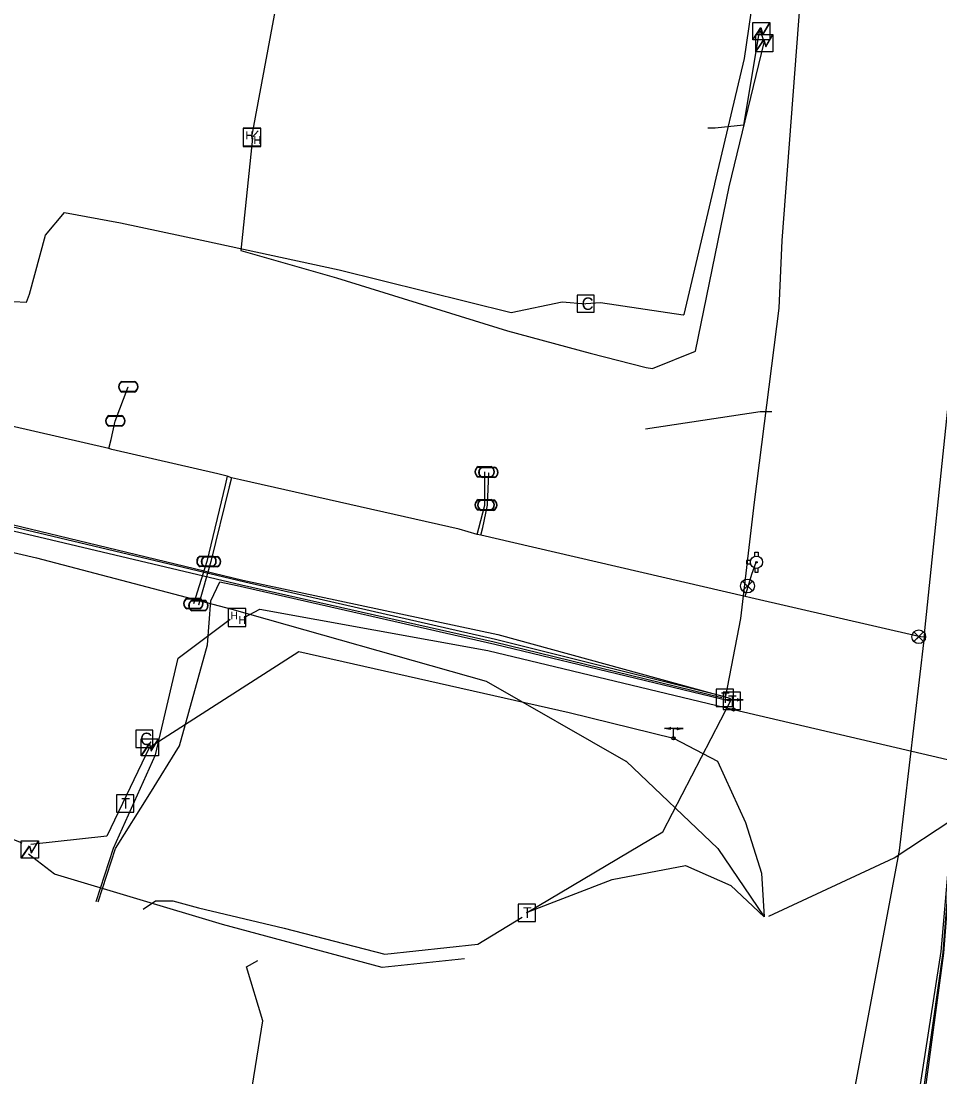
# Model space of a CAD drawing. Extents: x 2070721 to 2083039, y 729290 to 737883.
# Drawn here: x 2082067.8 to 2082364.3, y 736148.2 to 736489 of the extents above; entities that cross this region are included whole.
import ezdxf

# ---------------------------------------------------------------- set-up
doc = ezdxf.new("R2010")
doc.units = 0
for name, color, linetype in [('Cogo Default Point CELL', 7, 'Continuous'), ('COGO Default Point Elevation', 7, 'Continuous'), ('COGO Default Point Number', 7, 'Continuous'), ('Exist Utilities Power Pole CELL', 7, 'Continuous'), ('Exist Utilities Power Pole Cogo Elevation', 7, 'Continuous'), ('Exist Utilities Power UG Cable Cogo Point CELL', 7, 'Continuous'), ('Exist Utilities Telephone UG Cable SUE LOS C Cogo Elevation', 7, 'Continuous'), ('Exist Utilities Telephone UG Cable SUE LOS C Cogo Number', 7, 'Continuous'), ('Exist Utilities Telephone UG FO Cogo Point CELL', 7, 'Continuous'), ('Exist Utilities Telephone UG FO SUE LOS B Cogo Comment', 7, 'Continuous'), ('Exist Utilities Telephone UG FO SUE LOS B Cogo Number', 7, 'Continuous'), ('Exist Utilities TV Pedestal Cogo Elevation', 7, 'Continuous'), ('Exist Utilities TV UG Cable Cogo Point CELL', 7, 'Continuous'), ('Exist Utilities TV UG Cable SUE LOS C Cogo Comment', 7, 'Continuous'), ('Exist Utilities TV UG Cable SUE LOS C Cogo Elevation', 7, 'Continuous'), ('Exist Utilities TV UG Cable SUE LOS C Cogo Point CELL', 7, 'Continuous'), ('Exist Utilities Water UG Line SUE Cogo Point CELL', 7, 'Continuous'), ('Exist Utilities Water UG Line SUE LOS B Cogo Number', 7, 'Continuous')]:
    doc.layers.add(name, color=color, linetype=linetype)

msp = doc.modelspace()

# ---------------------------------------------------------------- linework, layer by layer
at = {"layer": 'Cogo Default Point CELL'}
for p, q in [((2082249.96, 736397.77), (2082249.96, 736397.77)), ((2082107.52, 736257.33), (2082107.52, 736257.33))]:
    msp.add_line(p, q, dxfattribs=at)
for points in [[(2082247.18, 736394.99), (2082252.73, 736394.99), (2082252.73, 736400.54), (2082247.18, 736400.54), (2082247.18, 736394.99)], [(2082104.75, 736254.56), (2082110.3, 736254.56), (2082110.3, 736260.1), (2082104.75, 736260.1), (2082104.75, 736254.56)]]:
    msp.add_lwpolyline(points, dxfattribs=at)
at = {"layer": 'COGO Default Point Elevation'}
for points in [[(2082303.77, 736308.23), (2082300.61, 736305.08), (2082302.19, 736306.66), (2082303.77, 736305.08), (2082300.61, 736308.23)], [(2082359.02, 736291.86), (2082355.86, 736288.71), (2082357.44, 736290.29), (2082359.02, 736288.71), (2082355.86, 736291.86)]]:
    msp.add_lwpolyline(points, dxfattribs=at)
for centre in [(2082302.19, 736306.66), (2082357.44, 736290.29)]:
    msp.add_circle(centre, 2.23, dxfattribs=at)
at = {"layer": 'COGO Default Point Number'}
msp.add_line((2082305.08, 736314.34), (2082305.08, 736314.34), dxfattribs=at)
for points in [[(2082303.17, 736314.85), (2082301.88, 736314.85), (2082301.88, 736313.83), (2082303.17, 736313.83)], [(2082304.57, 736316.25), (2082304.57, 736317.54), (2082305.59, 736317.54), (2082305.59, 736316.23)], [(2082304.57, 736312.43), (2082304.57, 736311.14), (2082305.59, 736311.14), (2082305.59, 736312.45)]]:
    msp.add_lwpolyline(points, dxfattribs=at)
for radius in [1.98, 0.243]:
    msp.add_circle((2082305.08, 736314.34), radius, dxfattribs=at)
at = {"layer": 'Exist Utilities Power Pole CELL'}
for points in [[(2082121.11, 735111.12), (2082125.96, 735163.62), (2082138.7, 735257.13), (2082145.62, 735320.66), (2082168.01, 735429.9), (2082199.18, 735564.38), (2082231.58, 735685.7), (2082254.18, 735727.05), (2082277.17, 735809.42), (2082316.95, 735921.54), (2082334, 735994.14), (2082349.07, 736088.38), (2082364.7, 736188.68), (2082369.94, 736249.54)], [(2082122.2, 735109.35), (2082127.71, 735163.64), (2082140.55, 735257.07), (2082148.23, 735320.74), (2082172.1, 735428.75), (2082203.63, 735562.9), (2082234.11, 735686.98), (2082254.24, 735726.85), (2082280.4, 735808.61), (2082320.45, 735920.23), (2082334.66, 735993.58), (2082351.98, 736087.59), (2082365.57, 736188.21), (2082370.28, 736249.44)]]:
    msp.add_lwpolyline(points, dxfattribs=at)
at = {"layer": 'Exist Utilities Power Pole Cogo Elevation'}
msp.add_lwpolyline([(2082278.27, 736257.54), (2082292.55, 736250.13), (2082301.58, 736230.36), (2082306.66, 736213.99), (2082307.6, 736199.94)], dxfattribs=at)
at = {"layer": 'Exist Utilities Power UG Cable Cogo Point CELL'}
for p, q in [((2082281.41, 736260.62), (2082275.44, 736260.62)), ((2082278.27, 736257.54), (2082278.27, 736260.62)), ((2082278.27, 736260.62), (2082281.41, 736260.62)), ((2082278.27, 736257.54), (2082278.27, 736257.54))]:
    msp.add_line(p, q, dxfattribs=at)
for points in [[(2082275.44, 736260.62), (2082277.41, 736260.97), (2082276.99, 736260.62), (2082277.38, 736260.32)], [(2082281.41, 736260.62), (2082279.43, 736260.28), (2082279.85, 736260.62), (2082279.47, 736260.93)]]:
    msp.add_lwpolyline(points, close=True, dxfattribs=at)
msp.add_circle((2082278.27, 736257.54), 0.517, dxfattribs=at)
at = {"layer": 'Exist Utilities Telephone UG Cable SUE LOS C Cogo Elevation'}
for p, q in [((2082142.36, 736451.38), (2082142.36, 736451.38)), ((2082142.38, 736451.24), (2082142.38, 736451.24))]:
    msp.add_line(p, q, dxfattribs=at)
for points in [[(2082139.41, 736448.66), (2082145.16, 736448.66), (2082145.16, 736454.41), (2082139.41, 736454.41), (2082139.41, 736448.66)], [(2082139.43, 736448.52), (2082145.18, 736448.52), (2082145.18, 736454.27), (2082139.43, 736454.27), (2082139.43, 736448.52)]]:
    msp.add_lwpolyline(points, dxfattribs=at)
at = {"layer": 'Exist Utilities Telephone UG Cable SUE LOS C Cogo Number'}
for p, q in [((2082306.73, 736485.89), (2082306.73, 736485.89)), ((2082307.68, 736482.03), (2082307.68, 736482.03)), ((2082109.36, 736254.78), (2082109.36, 736254.78)), ((2082070.65, 736221.81), (2082070.65, 736221.81))]:
    msp.add_line(p, q, dxfattribs=at)
for points in [[(2082303.88, 736488.5), (2082309.44, 736488.5), (2082309.44, 736482.95), (2082303.88, 736482.95)], [(2082304.84, 736484.64), (2082310.39, 736484.64), (2082310.39, 736479.09), (2082304.84, 736479.09)], [(2082106.52, 736257.39), (2082112.07, 736257.39), (2082112.07, 736251.84), (2082106.52, 736251.84)], [(2082067.81, 736224.42), (2082073.36, 736224.42), (2082073.36, 736218.87), (2082067.81, 736218.87)]]:
    msp.add_lwpolyline(points, close=True, dxfattribs=at)
for points in [[(2082303.88, 736482.95), (2082306.53, 736486.89), (2082307.16, 736484.68), (2082309.44, 736488.5)], [(2082303.95, 736482.95), (2082306.53, 736486.68), (2082307.11, 736484.5), (2082309.44, 736488.34)], [(2082304.84, 736479.09), (2082307.48, 736483.03), (2082308.11, 736480.82), (2082310.39, 736484.64)], [(2082304.91, 736479.09), (2082307.48, 736482.82), (2082308.07, 736480.64), (2082310.39, 736484.49)], [(2082106.52, 736251.84), (2082109.16, 736255.78), (2082109.79, 736253.57), (2082112.07, 736257.39)], [(2082106.59, 736251.84), (2082109.16, 736255.57), (2082109.75, 736253.39), (2082112.07, 736257.24)], [(2082067.81, 736218.87), (2082070.45, 736222.81), (2082071.08, 736220.6), (2082073.36, 736224.42)], [(2082067.88, 736218.87), (2082070.45, 736222.6), (2082071.04, 736220.42), (2082073.36, 736224.27)]]:
    msp.add_lwpolyline(points, dxfattribs=at)
at = {"layer": 'Exist Utilities Telephone UG FO Cogo Point CELL'}
for p, q in [((2082102.36, 736370.96), (2082102.36, 736370.96)), ((2082098.17, 736359.95), (2082098.17, 736359.95)), ((2082217.35, 736343.5), (2082217.35, 736343.5)), ((2082218.59, 736343.33), (2082218.59, 736343.33)), ((2082217.36, 736332.83), (2082217.36, 736332.83)), ((2082218.23, 736332.76), (2082218.23, 736332.76)), ((2082127.6, 736314.6), (2082127.6, 736314.6)), ((2082129.07, 736314.52), (2082129.07, 736314.52)), ((2082123.36, 736300.98), (2082123.36, 736300.98)), ((2082125, 736300.36), (2082125, 736300.36))]:
    msp.add_line(p, q, dxfattribs=at)
for points in [[(2082100.32, 736372.66), (2082104.4, 736372.66)], [(2082104.4, 736369.4), (2082100.3, 736369.4)], [(2082104.4, 736369.26), (2082100.3, 736369.26)], [(2082100.32, 736372.52), (2082104.4, 736372.52)], [(2082096.13, 736361.65), (2082100.21, 736361.65)], [(2082096.13, 736361.51), (2082100.21, 736361.51)], [(2082100.21, 736358.39), (2082096.11, 736358.39)], [(2082100.21, 736358.25), (2082096.11, 736358.25)], [(2082215.31, 736345.2), (2082219.39, 736345.2)], [(2082215.31, 736345.06), (2082219.39, 736345.06)], [(2082216.55, 736345.03), (2082220.63, 736345.03)], [(2082216.55, 736344.89), (2082220.63, 736344.89)], [(2082219.39, 736341.94), (2082215.29, 736341.94)], [(2082219.39, 736341.8), (2082215.29, 736341.8)], [(2082220.63, 736341.77), (2082216.53, 736341.77)], [(2082220.63, 736341.63), (2082216.53, 736341.63)], [(2082215.32, 736334.53), (2082219.4, 736334.53)], [(2082215.32, 736334.39), (2082219.4, 736334.39)], [(2082216.19, 736334.46), (2082220.27, 736334.46)], [(2082216.19, 736334.32), (2082220.27, 736334.32)], [(2082219.4, 736331.27), (2082215.3, 736331.27)], [(2082219.4, 736331.13), (2082215.3, 736331.13)], [(2082220.27, 736331.2), (2082216.17, 736331.2)], [(2082220.27, 736331.06), (2082216.17, 736331.06)], [(2082125.56, 736316.3), (2082129.64, 736316.3)], [(2082125.56, 736316.16), (2082129.64, 736316.16)], [(2082127.03, 736316.22), (2082131.11, 736316.22)], [(2082127.03, 736316.08), (2082131.11, 736316.08)], [(2082129.64, 736313.04), (2082125.54, 736313.04)], [(2082129.64, 736312.9), (2082125.54, 736312.9)], [(2082131.11, 736312.96), (2082127.01, 736312.96)], [(2082131.11, 736312.82), (2082127.01, 736312.82)], [(2082121.32, 736302.68), (2082125.4, 736302.68)], [(2082121.32, 736302.54), (2082125.4, 736302.54)], [(2082122.96, 736302.06), (2082127.04, 736302.06)], [(2082122.96, 736301.92), (2082127.04, 736301.92)], [(2082125.4, 736299.42), (2082121.3, 736299.42)], [(2082125.4, 736299.28), (2082121.3, 736299.28)], [(2082127.04, 736298.8), (2082122.94, 736298.8)], [(2082127.04, 736298.66), (2082122.94, 736298.66)]]:
    msp.add_lwpolyline(points, dxfattribs=at)
for centre, radius, start, end in [((2082101.05, 736370.95), 1.86, 113.178, 245.9794), ((2082103.65, 736370.96), 1.86, 293.6483, 66.3084), ((2082101.06, 736370.95), 1.73, 115.3009, 243.7824), ((2082103.66, 736370.96), 1.73, 295.1272, 64.8728), ((2082096.86, 736359.94), 1.86, 113.178, 245.9794), ((2082096.87, 736359.94), 1.73, 115.3009, 243.7824), ((2082099.46, 736359.95), 1.86, 293.6483, 66.3084), ((2082099.47, 736359.95), 1.73, 295.1272, 64.8728), ((2082216.04, 736343.49), 1.86, 113.178, 245.9794), ((2082216.05, 736343.49), 1.73, 115.3009, 243.7824), ((2082217.28, 736343.32), 1.86, 113.178, 245.9794), ((2082217.29, 736343.32), 1.73, 115.3009, 243.7824), ((2082218.64, 736343.5), 1.86, 293.6483, 66.3084), ((2082218.65, 736343.5), 1.73, 295.1272, 64.8728), ((2082219.88, 736343.33), 1.86, 293.6483, 66.3084), ((2082219.89, 736343.33), 1.73, 295.1272, 64.8728), ((2082216.05, 736332.82), 1.86, 113.178, 245.9794), ((2082216.06, 736332.82), 1.73, 115.3009, 243.7824), ((2082216.92, 736332.75), 1.86, 113.178, 245.9794), ((2082216.93, 736332.75), 1.73, 115.3009, 243.7824), ((2082218.65, 736332.83), 1.86, 293.6483, 66.3084), ((2082218.66, 736332.83), 1.73, 295.1272, 64.8728), ((2082219.52, 736332.76), 1.86, 293.6483, 66.3084), ((2082219.53, 736332.76), 1.73, 295.1272, 64.8728), ((2082126.29, 736314.59), 1.86, 113.178, 245.9794), ((2082126.3, 736314.59), 1.73, 115.3009, 243.7824), ((2082127.76, 736314.51), 1.86, 113.178, 245.9794), ((2082127.77, 736314.51), 1.73, 115.3009, 243.7824), ((2082128.89, 736314.6), 1.86, 293.6483, 66.3084), ((2082128.9, 736314.6), 1.73, 295.1272, 64.8728), ((2082130.36, 736314.52), 1.86, 293.6483, 66.3084), ((2082130.37, 736314.52), 1.73, 295.1272, 64.8728), ((2082122.05, 736300.97), 1.86, 113.178, 245.9794), ((2082122.06, 736300.97), 1.73, 115.3009, 243.7824), ((2082123.69, 736300.35), 1.86, 113.178, 245.9794), ((2082123.7, 736300.35), 1.73, 115.3009, 243.7824), ((2082124.65, 736300.98), 1.86, 293.6483, 66.3084), ((2082124.66, 736300.98), 1.73, 295.1272, 64.8728), ((2082126.29, 736300.36), 1.86, 293.6483, 66.3084), ((2082126.3, 736300.36), 1.73, 295.1272, 64.8728)]:
    msp.add_arc(centre, radius, start, end, dxfattribs=at)
at = {"layer": 'Exist Utilities Telephone UG FO SUE LOS B Cogo Comment'}
for p, q in [((2082294.79, 736270.59), (2082294.79, 736270.59)), ((2082297.01, 736269.62), (2082297.01, 736269.62)), ((2082101.28, 736236.51), (2082101.28, 736236.51)), ((2082230.86, 736201.26), (2082230.86, 736201.26))]:
    msp.add_line(p, q, dxfattribs=at)
for points in [[(2082292.07, 736267.76), (2082297.66, 736267.76), (2082297.66, 736273.36), (2082292.07, 736273.36), (2082292.07, 736267.76)], [(2082294.29, 736266.79), (2082299.88, 736266.79), (2082299.88, 736272.39), (2082294.29, 736272.39), (2082294.29, 736266.79)], [(2082098.56, 736233.68), (2082104.15, 736233.68), (2082104.15, 736239.28), (2082098.56, 736239.28), (2082098.56, 736233.68)], [(2082228.14, 736198.43), (2082233.73, 736198.43), (2082233.73, 736204.03), (2082228.14, 736204.03), (2082228.14, 736198.43)]]:
    msp.add_lwpolyline(points, dxfattribs=at)
at = {"layer": 'Exist Utilities Telephone UG FO SUE LOS B Cogo Number'}
for p, q in [((2082134.54, 736299.36), (2082134.54, 736293.64)), ((2082140.26, 736299.36), (2082134.54, 736299.36)), ((2082140.26, 736293.64), (2082140.26, 736299.36)), ((2082137.4, 736296.5), (2082137.4, 736296.5)), ((2082134.54, 736293.64), (2082140.26, 736293.64))]:
    msp.add_line(p, q, dxfattribs=at)
at = {"layer": 'Exist Utilities TV Pedestal Cogo Elevation'}
for points in [[(2082359.3, 736290.13), (2082359.45, 736292.32), (2082374.67, 736439.46), (2082381.09, 736508.57), (2082384.35, 736558.86)], [(2082096.13, 736351.01), (2082096.83, 736353.98), (2082098.08, 736359.89), (2082102.34, 736370.98)], [(2082096.13, 736351.01), (2082024.3, 736367.53)], [(2082131.26, 736342.83), (2082097.1, 736350.7), (2082096.13, 736351.01)], [(2082134.24, 736342.06), (2082133.57, 736339.25), (2082127.69, 736314.54), (2082123.39, 736300.94)], [(2082135.62, 736341.57), (2082134.24, 736342.06), (2082131.26, 736342.83)], [(2082214.95, 736323.31), (2082215.49, 736325.35), (2082217.47, 736332.78), (2082217.41, 736343.47)], [(2082216.16, 736323.06), (2082216.72, 736325.51), (2082218.24, 736332.74), (2082218.7, 736343.21)], [(2082135.62, 736341.57), (2082134.96, 736338.69), (2082129.02, 736314.54), (2082124.97, 736300.43)], [(2082214.95, 736323.31), (2082209.11, 736324.97), (2082138.6, 736340.96), (2082135.62, 736341.57)], [(2082216.16, 736323.06), (2082214.95, 736323.31)], [(2082301.46, 736303.24), (2082226.74, 736320.57), (2082216.16, 736323.06)], [(2082301.46, 736303.24), (2082303.57, 736310.44), (2082305, 736314.34)], [(2082359.3, 736290.13), (2082358.07, 736290.29), (2082357.52, 736290.36), (2082303.24, 736302.85), (2082301.46, 736303.24)], [(2082320.68, 735936.86), (2082316.05, 736027.92), (2082334.72, 736133.01), (2082351.23, 736221.26), (2082359.3, 736290.13)]]:
    msp.add_lwpolyline(points, dxfattribs=at)
at = {"layer": 'Exist Utilities TV UG Cable Cogo Point CELL'}
for points in [[(2082313.36, 736418.13), (2082323.5, 736551.56), (2082325.19, 736575.84), (2082324.51, 736589.38), (2082321.65, 736591.13), (2082314.03, 736592.42), (2082290.9, 736590.33)], [(2081568.17, 736468.83), (2081615.92, 736445.96), (2081696.31, 736415.49), (2081804.57, 736385.24), (2081915.03, 736359.08), (2081987.17, 736342.62), (2082073.48, 736322.55), (2082138.89, 736307.01), (2082220.41, 736288.62), (2082293.92, 736270.7)], [(2081568.48, 736469.51), (2081618.39, 736447.85), (2081696.88, 736418.07), (2081805.87, 736388.07), (2081916.17, 736362.01), (2081987.94, 736345.05), (2082073.78, 736324.33), (2082139.32, 736308.59), (2082221.63, 736291.02), (2082296.5, 736270.5)], [(2081615.72, 736447.72), (2081617.75, 736446.75), (2081696.77, 736417.12), (2081805.08, 736386.54), (2081915.58, 736360.92), (2081915.48, 736360.89), (2081987.51, 736343.92), (2082073.49, 736323.81), (2082139.92, 736308.03), (2082220.81, 736289.54), (2082294.45, 736271.08)], [(2082295.23, 736271.11), (2082300.01, 736296.17), (2082304.41, 736333.72), (2082312.38, 736396.33), (2082313.36, 736418.13)], [(2082092.68, 736204.69), (2082098.21, 736221.96), (2082109.36, 736239.64), (2082118.86, 736255.05), (2082127.88, 736287.62), (2082128.99, 736301.9), (2082131.92, 736308.02), (2082137.48, 736306.8), (2082220.68, 736287.9), (2082296.51, 736269.59)], [(2082230.87, 736201.17), (2082274.89, 736227.31), (2082296.74, 736269.44)], [(2082309.03, 736200.13), (2082349.47, 736218.89), (2082368.17, 736231.22), (2082370.24, 736249.61), (2082392.9, 736262.1)], [(2082230.86, 736201.26), (2082258.55, 736211.96), (2082282.14, 736216.42), (2082296.8, 736210.02), (2082307.6, 736199.94)], [(2082107.12, 736202.32), (2082111.17, 736205.08), (2082116.7, 736205.08), (2082124.99, 736202.78), (2082152.65, 736196.19), (2082185.11, 736187.86), (2082215.2, 736191.06), (2082229.49, 736199.82)]]:
    msp.add_lwpolyline(points, dxfattribs=at)
at = {"layer": 'Exist Utilities TV UG Cable SUE LOS C Cogo Comment'}
for p, q in [((2082307.68, 736482.03), (2082306.13, 736486.24)), ((2082142.32, 736451.4), (2082144.32, 736453.59))]:
    msp.add_line(p, q, dxfattribs=at)
for points in [[(2082142.24, 736451.57), (2082149.5, 736490.83), (2082151.41, 736499.09)], [(2082305.96, 736485.62), (2082300.89, 736455.33), (2082291.77, 736454.45), (2082289.34, 736454.45)], [(2082271.53, 736376.84), (2082285.41, 736382.49), (2082296.3, 736435.5), (2082307.51, 736482.11)], [(2082142.46, 736451.19), (2082138.63, 736414.9), (2082169.51, 736406.15), (2082224.78, 736389.04), (2082251.44, 736381.79), (2082269.44, 736377.14), (2082271.53, 736376.84)], [(2082269.25, 736357.35), (2082306.32, 736362.94), (2082308.86, 736362.94), (2082310.07, 736362.94)], [(2082109.4, 736254.71), (2082157.41, 736285.53), (2082244.68, 736265.83), (2082278.27, 736257.54)], [(2082008.8, 736279.06), (2082001.18, 736250.65), (2082068.04, 736223.8)], [(2082109.16, 736254.62), (2082095.38, 736225.9), (2082070.95, 736223.19)], [(2082210.82, 736186.38), (2082184.27, 736183.56), (2082132.77, 736197.39), (2082078.53, 736213.65), (2082070.12, 736220.15)], [(2082110.71, 735996.86), (2082120.65, 736037.47), (2082135.66, 736103.41), (2082145.82, 736166.3), (2082140.52, 736183.81), (2082144.17, 736185.75)]]:
    msp.add_lwpolyline(points, dxfattribs=at)
at = {"layer": 'Exist Utilities TV UG Cable SUE LOS C Cogo Elevation'}
msp.add_line((2082281.76, 736394.25), (2082291.67, 736436.35), dxfattribs=at)
for points in [[(2082291.62, 736436.42), (2082301.26, 736476.92), (2082307.72, 736521.26), (2082314.13, 736551.45), (2082318.86, 736581.32), (2082318.86, 736581.32)], [(2081867.92, 736374.85), (2081908.54, 736402.92), (2081922.2, 736410.85), (2081955.72, 736410.85), (2081976.56, 736410.85), (2082011.49, 736410.85), (2082028.68, 736408.17), (2082065.29, 736398.47), (2082069.56, 736398.28), (2082070.52, 736400.88), (2082075.6, 736419.83), (2082081.77, 736427.24), (2082099.8, 736423.88), (2082126.06, 736418.32), (2082170.39, 736408.66), (2082225.96, 736394.95), (2082242.36, 736398.41), (2082249.96, 736397.77)], [(2082281.76, 736394.25), (2082281.45, 736394.01), (2082254.75, 736398.03), (2082249.96, 736397.77)], [(2081867.92, 736374.85), (2081869.92, 736367.25), (2081876.67, 736362.95), (2081888.78, 736359.07), (2081912.22, 736353.44), (2081986.37, 736335.81), (2082072.78, 736315.77), (2082135.75, 736299.21), (2082217.86, 736275.92), (2082262.9, 736250.17), (2082262.99, 736250.08), (2082292.59, 736221.95), (2082307.6, 736199.94)]]:
    msp.add_lwpolyline(points, dxfattribs=at)
at = {"layer": 'Exist Utilities TV UG Cable SUE LOS C Cogo Point CELL'}
for points in [[(2082139.75, 736296.47), (2082144.85, 736299.13), (2082218.4, 736285.8), (2082297.68, 736266.81)], [(2082091.94, 736204.81), (2082097.62, 736222.03), (2082111.17, 736252.22), (2082118.46, 736283.41), (2082135.22, 736295.91)], [(2082120.86, 735106.65), (2082121.53, 735109.26), (2082126.82, 735163.37), (2082139.88, 735257.28), (2082147.13, 735321.1), (2082170.45, 735428.84), (2082201.87, 735563.79), (2082232.74, 735685.94), (2082254.12, 735726.65), (2082278.69, 735809.1), (2082319.03, 735920.81), (2082334.41, 735993.71), (2082351.13, 736088.05), (2082365.28, 736188.35), (2082370.12, 736249.49)]]:
    msp.add_lwpolyline(points, dxfattribs=at)
at = {"layer": 'Exist Utilities Water UG Line SUE Cogo Point CELL'}
for p, q in [((2082300.82, 736269.89), (2082294.85, 736269.89)), ((2082297.68, 736266.81), (2082297.68, 736269.89)), ((2082297.68, 736269.89), (2082300.82, 736269.89)), ((2082297.68, 736266.81), (2082297.68, 736266.81))]:
    msp.add_line(p, q, dxfattribs=at)
for points in [[(2082294.85, 736269.89), (2082296.82, 736270.24), (2082296.4, 736269.89), (2082296.79, 736269.59)], [(2082300.82, 736269.89), (2082298.84, 736269.55), (2082299.26, 736269.89), (2082298.88, 736270.2)]]:
    msp.add_lwpolyline(points, close=True, dxfattribs=at)
msp.add_circle((2082297.68, 736266.81), 0.517, dxfattribs=at)
at = {"layer": 'Exist Utilities Water UG Line SUE LOS B Cogo Number'}
msp.add_line((2082297.68, 736266.81), (2082369.98, 736249.96), dxfattribs=at)

# ---------------------------------------------------------------- texts
at = {"layer": 'Cogo Default Point CELL'}
for p in [(2082248.65, 736395.77), (2082106.21, 736255.33)]:
    msp.add_text('C', height=4, dxfattribs=at).set_placement(p)
at = {"layer": 'Exist Utilities Telephone UG Cable SUE LOS C Cogo Elevation'}
for p in [(2082140.2, 736450.91), (2082140.22, 736450.77), (2082142.77, 736449.39), (2082142.79, 736449.25)]:
    msp.add_text('H', height=2.5, dxfattribs=at).set_placement(p)
at = {"layer": 'Exist Utilities Telephone UG FO SUE LOS B Cogo Comment'}
for p in [(2082293.66, 736268.88), (2082295.88, 736267.91), (2082100.15, 736234.8), (2082229.73, 736199.55)]:
    msp.add_text('T', height=3.42, dxfattribs=at).set_placement(p)
at = {"layer": 'Exist Utilities Telephone UG FO SUE LOS B Cogo Number'}
for p in [(2082135.32, 736295.91), (2082137.89, 736294.44)]:
    msp.add_text('H', height=2.5, dxfattribs=at).set_placement(p)

doc.saveas('drawing.dxf')
